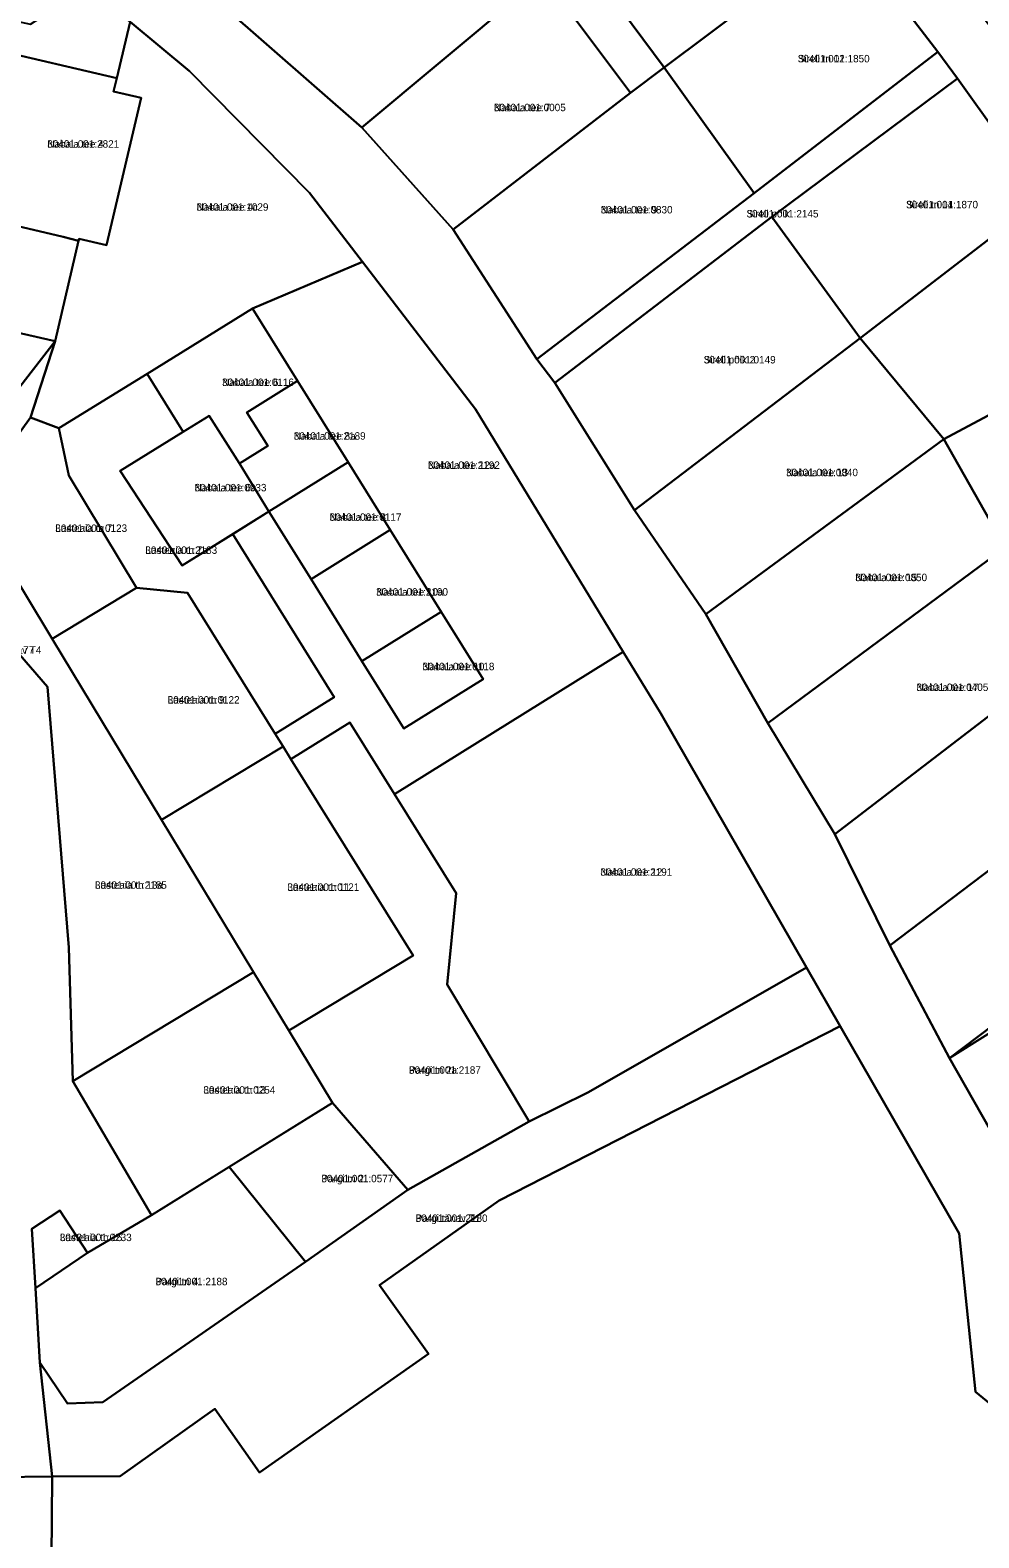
# Model space of a CAD drawing. Extents: x 542681 to 554572, y 6566489 to 6580482.
# Drawn here: x 547681.6 to 547873, y 6574390.7 to 6574695.1 of the extents above; entities that cross this region are included whole.
import ezdxf

# ---------------------------------------------------------------- set-up
doc = ezdxf.new("R2010")
doc.units = 0
for name, color, linetype in [('L_AADRESS', 7, 'Continuous'), ('PIIR', 7, 'Continuous'), ('TUNNUS', 7, 'Continuous')]:
    doc.layers.add(name, color=color, linetype=linetype)

msp = doc.modelspace()

# ---------------------------------------------------------------- linework, layer by layer
at = {"layer": 'PIIR'}
for points in [[(547476.06, 6574925.9), (547527.94, 6574880.26), (547559.79, 6574851.89), (547556.38, 6574841.75), (547562.1, 6574836.76), (547583.39, 6574818.2), (547604.29, 6574799.92), (547649.49, 6574760.46), (547649.99, 6574760.02), (547686.6, 6574735.31), (547720.19, 6574700.15), (547748.47, 6574675.44), (547766.88, 6574654.86), (547783.77, 6574628.63), (547787.43, 6574623.85), (547803.48, 6574598.2), (547817.86, 6574577.17), (547830.41, 6574555.16), (547843.88, 6574532.73), (547855.03, 6574510.31), (547867.02, 6574487.55), (547880.23, 6574464.33)], [(547897.66, 6574399.47), (547872.32, 6574420.2), (547869, 6574452.12), (547845, 6574493.98), (547838.18, 6574505.87), (547808.78, 6574557.14), (547801.21, 6574569.57), (547771.38, 6574618.58), (547748.61, 6574648.28), (547737.92, 6574662.22), (547713.69, 6574686.8), (547701.71, 6574696.78), (547693.24, 6574703.84), (547668.51, 6574724.43), (547643.28, 6574741.46), (547622.15, 6574762.88), (547606.39, 6574776.28), (547584.22, 6574795.13), (547573.33, 6574804.26), (547532.2, 6574839.13), (547518.45, 6574850.21), (547495.77, 6574869.26), (547470.01, 6574890.87), (547435.57, 6574921.6)], [(547885.89, 6574661.24), (547868.68, 6574685.34), (547864.7, 6574690.66), (547846.06, 6574714.98), (547826.55, 6574741.44), (547806.81, 6574766.19), (547768.39, 6574814.6), (547758.03, 6574838.36), (547750.11, 6574858.42), (547741.38, 6574880.61), (547734.63, 6574886.42), (547754.87, 6574883.28), (547752.87, 6574878.71), (547766.39, 6574842.31), (547776.34, 6574818.39), (547797.15, 6574794.34), (547822.4, 6574763.04), (547824.24, 6574760.56), (547825.95, 6574758.28), (547844.69, 6574734.97), (547862.95, 6574711.67), (547881.42, 6574687.96)], [(547880.23, 6574464.33), (547867.02, 6574487.55), (547912.35, 6574515.93)]]:
    msp.add_lwpolyline(points, dxfattribs=at)
for points in [[(547816.08, 6574733.94), (547826.55, 6574741.44), (547846.06, 6574714.98), (547809.48, 6574687.51), (547790.28, 6574713.35)], [(547570.79, 6574730.49), (547571.21, 6574724.16), (547573.28, 6574719.74), (547681.62, 6574696.3), (547693.24, 6574703.84), (547701.71, 6574696.78), (547699.02, 6574685.37), (547673.6, 6574691.27), (547670.48, 6574677.72), (547644.79, 6574683.65), (547603.92, 6574693.1), (547606.83, 6574705.08), (547564.79, 6574715.05)], [(547780.68, 6574705.67), (547780.86, 6574702.55), (547748.47, 6574675.44), (547720.19, 6574700.15), (547732.44, 6574709.56), (547759.27, 6574730.19)], [(547864.7, 6574690.66), (547827.65, 6574662.16), (547809.48, 6574687.51), (547846.06, 6574714.98)], [(547780.68, 6574705.67), (547790.28, 6574713.35), (547809.48, 6574687.51), (547802.7, 6574682.43), (547788.13, 6574701.89), (547780.86, 6574702.55)], [(547780.86, 6574702.55), (547788.13, 6574701.89), (547802.7, 6574682.43), (547766.88, 6574654.86), (547748.47, 6574675.44)], [(547701.71, 6574696.78), (547713.69, 6574686.8), (547737.92, 6574662.22), (547748.61, 6574648.28), (547726.41, 6574638.91), (547705.16, 6574625.69), (547687.32, 6574614.71), (547681.65, 6574616.89), (547686.63, 6574632.27), (547691.33, 6574652.54), (547691.43, 6574652.97), (547696.95, 6574651.68), (547703.97, 6574681.38), (547698.4, 6574682.68), (547699.02, 6574685.37)], [(547666.08, 6574658.52), (547670.48, 6574677.72), (547673.6, 6574691.27), (547699.02, 6574685.37), (547698.4, 6574682.68), (547703.97, 6574681.38), (547696.95, 6574651.68), (547691.43, 6574652.97), (547691.33, 6574652.54), (547688.21, 6574653.33), (547675.3, 6574656.35)], [(547787.43, 6574623.85), (547783.77, 6574628.63), (547827.65, 6574662.16), (547864.7, 6574690.66), (547868.68, 6574685.34), (547831.17, 6574657.39)], [(547827.65, 6574662.16), (547783.77, 6574628.63), (547766.88, 6574654.86), (547802.7, 6574682.43), (547809.48, 6574687.51)], [(547670.48, 6574677.72), (547666.08, 6574658.52), (547675.3, 6574656.35), (547688.21, 6574653.33), (547691.33, 6574652.54), (547686.63, 6574632.27), (547635.74, 6574643.87), (547644.79, 6574683.65)], [(547885.89, 6574661.24), (547849.05, 6574632.88), (547831.17, 6574657.39), (547868.68, 6574685.34)], [(547686.63, 6574632.27), (547679.49, 6574623.06), (547657.17, 6574628.16), (547652.97, 6574629.12), (547647.28, 6574630.67), (547569.49, 6574648.27), (547568.57, 6574643.82), (547549, 6574632.04), (547570.61, 6574596.39), (547564.66, 6574597.51), (547543.35, 6574632.67), (547558.04, 6574641.6), (547560.19, 6574651.29), (547543.94, 6574654.09), (547486.8, 6574667.15), (547521.8, 6574677.56), (547595.88, 6574660.3), (547594.5, 6574654.66), (547635.74, 6574643.87)], [(547905.09, 6574633.4), (547865.88, 6574612.52), (547849.05, 6574632.88), (547885.89, 6574661.24)], [(547803.48, 6574598.2), (547787.43, 6574623.85), (547831.17, 6574657.39), (547849.05, 6574632.88)], [(547726.41, 6574638.91), (547748.61, 6574648.28), (547771.38, 6574618.58), (547801.21, 6574569.57), (547755.05, 6574540.86), (547746.07, 6574555.3), (547734.18, 6574547.9), (547732.6, 6574550.45), (547731.02, 6574553), (547742.9, 6574560.39), (547722.42, 6574593.33), (547729.72, 6574597.88), (547738.22, 6574584.22), (547748.5, 6574567.67), (547756.93, 6574554.1), (547772.94, 6574564.05), (547764.51, 6574577.62), (547754.22, 6574594.17), (547745.73, 6574607.83), (547735.51, 6574624.27)], [(547735.51, 6574624.27), (547725.28, 6574617.91), (547729.49, 6574611.13), (547723.76, 6574607.57), (547717.7, 6574617.23), (547712.45, 6574613.97), (547705.16, 6574625.69), (547726.41, 6574638.91)], [(547662.66, 6574581.02), (547644.58, 6574582.24), (547660.86, 6574592.15), (547667.67, 6574607.5), (547656.22, 6574624.37), (547657.17, 6574628.16), (547679.49, 6574623.06), (547686.63, 6574632.27), (547681.65, 6574616.89), (547673.14, 6574605.15), (547670.2, 6574598.38)], [(547849.05, 6574632.88), (547865.88, 6574612.52), (547817.86, 6574577.17), (547803.48, 6574598.2)], [(547905.09, 6574633.4), (547921.35, 6574606.93), (547880.7, 6574586.31), (547878.27, 6574590.6), (547865.88, 6574612.52)], [(547687.32, 6574614.71), (547705.16, 6574625.69), (547712.45, 6574613.97), (547699.74, 6574606.1), (547712.22, 6574586.99), (547722.42, 6574593.33), (547742.9, 6574560.39), (547731.02, 6574553), (547713.32, 6574581.45), (547703.04, 6574582.49), (547689.36, 6574605.14)], [(547725.28, 6574617.91), (547735.51, 6574624.27), (547745.73, 6574607.83), (547729.72, 6574597.88), (547723.76, 6574607.57), (547729.49, 6574611.13)], [(547687.32, 6574614.71), (547689.36, 6574605.14), (547703.04, 6574582.49), (547686, 6574572.2), (547670.2, 6574598.38), (547673.14, 6574605.15), (547681.65, 6574616.89)], [(547699.74, 6574606.1), (547712.45, 6574613.97), (547717.7, 6574617.23), (547723.76, 6574607.57), (547729.72, 6574597.88), (547712.22, 6574586.99)], [(547865.88, 6574612.52), (547878.27, 6574590.6), (547830.41, 6574555.16), (547817.86, 6574577.17)], [(547754.22, 6574594.17), (547738.22, 6574584.22), (547729.72, 6574597.88), (547745.73, 6574607.83)], [(547670.2, 6574598.38), (547686, 6574572.2), (547708.06, 6574535.64), (547726.61, 6574504.91), (547690.14, 6574482.87), (547689.34, 6574509.9), (547685.03, 6574562.47), (547672.56, 6574576.9), (547662.66, 6574581.02)], [(547738.22, 6574584.22), (547754.22, 6574594.17), (547764.51, 6574577.62), (547748.5, 6574567.67)], [(547878.27, 6574590.6), (547880.7, 6574586.31), (547890.63, 6574568.63), (547843.88, 6574532.73), (547830.41, 6574555.16)], [(547644.58, 6574582.24), (547662.66, 6574581.02), (547672.56, 6574576.9), (547685.03, 6574562.47), (547689.34, 6574509.9), (547690.14, 6574482.87), (547706.06, 6574455.86), (547693.15, 6574448.27), (547687.53, 6574456.77), (547681.92, 6574453.09), (547682.63, 6574441.14), (547683.52, 6574426.09), (547686.02, 6574403.1), (547674.8, 6574402.98), (547675.11, 6574438.37), (547674.49, 6574453.16), (547671.7, 6574518.5), (547667.72, 6574561.26), (547629.7, 6574568.1)], [(547713.32, 6574581.45), (547731.02, 6574553), (547732.6, 6574550.45), (547708.06, 6574535.64), (547686, 6574572.2), (547703.04, 6574582.49)], [(547772.94, 6574564.05), (547756.93, 6574554.1), (547748.5, 6574567.67), (547764.51, 6574577.62)], [(547755.05, 6574540.86), (547801.21, 6574569.57), (547808.78, 6574557.14), (547838.18, 6574505.87), (547794.2, 6574480.65), (547782.24, 6574474.77), (547765.66, 6574502.39), (547767.5, 6574520.85)], [(547855.03, 6574510.31), (547843.88, 6574532.73), (547890.63, 6574568.63), (547902.86, 6574546.55)], [(547734.18, 6574547.9), (547746.07, 6574555.3), (547755.05, 6574540.86), (547767.5, 6574520.85), (547765.66, 6574502.39), (547782.24, 6574474.77), (547757.79, 6574460.93), (547742.53, 6574478.55), (547733.74, 6574493.1), (547758.85, 6574508.25)], [(547758.85, 6574508.25), (547733.74, 6574493.1), (547708.06, 6574535.64), (547732.6, 6574550.45), (547734.18, 6574547.9)], [(547855.03, 6574510.31), (547902.86, 6574546.55), (547910.75, 6574531.81), (547914.68, 6574523.57), (547867.02, 6574487.55)], [(547912.35, 6574515.93), (547867.02, 6574487.55), (547914.68, 6574523.57), (547915.64, 6574521.88)], [(547683.52, 6574426.09), (547689.08, 6574417.8), (547696.24, 6574418.09), (547737.11, 6574446.43), (547757.79, 6574460.93), (547782.24, 6574474.77), (547794.2, 6574480.65), (547838.18, 6574505.87), (547845, 6574493.98), (547776.17, 6574458.79), (547752.03, 6574441.73), (547761.91, 6574427.82), (547727.86, 6574403.92), (547718.83, 6574416.77), (547699.71, 6574403.18), (547686.02, 6574403.1)], [(547726.61, 6574504.91), (547733.74, 6574493.1), (547742.53, 6574478.55), (547706.06, 6574455.86), (547690.14, 6574482.87)], [(547686.02, 6574403.1), (547699.71, 6574403.18), (547718.83, 6574416.77), (547727.86, 6574403.92), (547761.91, 6574427.82), (547752.03, 6574441.73), (547776.17, 6574458.79), (547845, 6574493.98), (547869, 6574452.12), (547872.32, 6574420.2), (547897.66, 6574399.47), (547946.32, 6574294.83), (547890.39, 6574270.78), (547827.72, 6574239.33), (547822.03, 6574250.5), (547734.02, 6574212.5), (547686.82, 6574244.56), (547684.85, 6574263.33)], [(547742.53, 6574478.55), (547757.79, 6574460.93), (547737.11, 6574446.43), (547721.7, 6574465.59)], [(547682.63, 6574441.14), (547693.15, 6574448.27), (547706.06, 6574455.86), (547721.7, 6574465.59), (547737.11, 6574446.43), (547696.24, 6574418.09), (547689.08, 6574417.8), (547683.52, 6574426.09)], [(547693.15, 6574448.27), (547682.63, 6574441.14), (547681.92, 6574453.09), (547687.53, 6574456.77)], [(547674.8, 6574402.98), (547686.02, 6574403.1), (547684.85, 6574263.33), (547686.82, 6574244.56), (547734.02, 6574212.5), (547822.03, 6574250.5), (547827.72, 6574239.33), (547809.69, 6574230.27), (547777.69, 6574214.19), (547733.83, 6574194.4), (547727.86, 6574183.54), (547715.37, 6574192.04), (547668.73, 6574223.8), (547673.47, 6574242.5), (547673.47, 6574243.11)]]:
    msp.add_lwpolyline(points, close=True, dxfattribs=at)

# ---------------------------------------------------------------- texts
at = {"layer": 'L_AADRESS'}
for s, p in [('Sireli tn 12', (547836.44, 6574688.57)), ('Nabala tee 7', (547775.12, 6574678.71)), ('Nabala tee 4', (547685.02, 6574671.35)), ('Nabala tee 4c', (547715.13, 6574658.62)), ('Nabala tee 9', (547796.67, 6574658.07)), ('Sireli tn 14', (547858.3, 6574659.11)), ('Sireli põik', (547826.11, 6574657.26)), ('Sireli põik 2', (547817.47, 6574627.79)), ('Nabala tee 6', (547720.27, 6574623.24)), ('Nabala tee 8a', (547734.74, 6574612.4)), ('Nabala tee 12a', (547761.82, 6574606.51)), ('Nabala tee 13', (547834.07, 6574605.03)), ('Nabala tee 6a', (547714.73, 6574601.97)), ('Lasteaia tn 7', (547686.62, 6574593.78)), ('Nabala tee 8', (547741.97, 6574596.02)), ('Lasteaia tn 7a', (547704.79, 6574589.35)), ('Nabala tee 15', (547848.03, 6574583.84)), ('Nabala tee 10a', (547751.36, 6574580.92)), ('Lasteaia tänav T4', (547667.88, 6574569.19)), ('Nabala tee 10', (547760.72, 6574565.86)), ('Nabala tee 17', (547860.38, 6574561.67)), ('Lasteaia tn 9', (547709.3, 6574559.12)), ('Nabala tee 12', (547796.61, 6574524.37)), ('Lasteaia tn 13a', (547694.63, 6574521.74)), ('Lasteaia tn 11', (547733.46, 6574521.32)), ('Pargi tn 2a', (547757.99, 6574484.39)), ('Lasteaia tn 13', (547716.51, 6574480.38)), ('Pargi tn 2', (547740.32, 6574462.49)), ('Pargi tänav T1', (547759.34, 6574454.49)), ('Lasteaia tn 15', (547687.54, 6574450.61)), ('Pargi tn 4', (547706.87, 6574441.7))]:
    msp.add_text(s, height=1.5, dxfattribs=at).set_placement(p)
at = {"layer": 'TUNNUS'}
for s, p in [('30401:001:1850', (547836.44, 6574688.57)), ('30401:001:0005', (547775.12, 6574678.71)), ('30401:001:2821', (547685.02, 6574671.35)), ('30401:001:1029', (547715.13, 6574658.62)), ('30401:001:0830', (547796.67, 6574658.07)), ('30401:001:1870', (547858.3, 6574659.11)), ('30401:001:2145', (547826.11, 6574657.26)), ('30401:001:0149', (547817.47, 6574627.79)), ('30401:001:0116', (547720.27, 6574623.24)), ('30401:001:2189', (547734.74, 6574612.4)), ('30401:001:2192', (547761.82, 6574606.51)), ('30401:001:0840', (547834.07, 6574605.03)), ('30401:001:0933', (547714.73, 6574601.97)), ('30401:001:0123', (547686.62, 6574593.78)), ('30401:001:0117', (547741.97, 6574596.02)), ('30401:001:2183', (547704.79, 6574589.35)), ('30401:001:0850', (547848.03, 6574583.84)), ('30401:001:2190', (547751.36, 6574580.92)), ('30401:001:2177', (547667.88, 6574569.19)), ('30401:001:0118', (547760.72, 6574565.86)), ('30401:001:0405', (547860.38, 6574561.67)), ('30401:001:0122', (547709.3, 6574559.12)), ('30401:001:2191', (547796.61, 6574524.37)), ('30401:001:2185', (547694.63, 6574521.74)), ('30401:001:0121', (547733.46, 6574521.32)), ('30401:001:2187', (547757.99, 6574484.39)), ('30401:001:0254', (547716.51, 6574480.38)), ('30401:001:0577', (547740.32, 6574462.49)), ('30401:001:2180', (547759.34, 6574454.49)), ('30401:001:0233', (547687.54, 6574450.61)), ('30401:001:2188', (547706.87, 6574441.7))]:
    msp.add_text(s, height=1.5, dxfattribs=at).set_placement(p)

doc.saveas('drawing.dxf')
